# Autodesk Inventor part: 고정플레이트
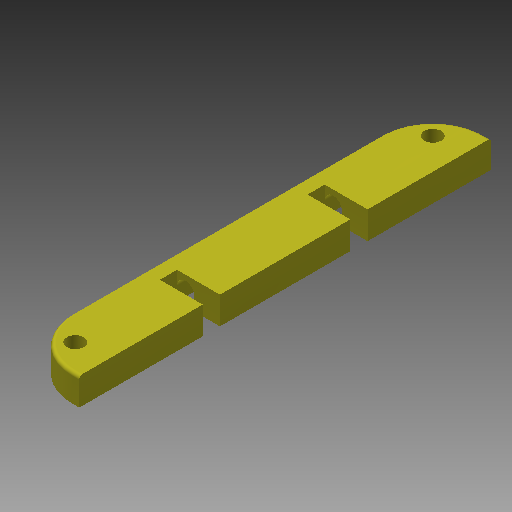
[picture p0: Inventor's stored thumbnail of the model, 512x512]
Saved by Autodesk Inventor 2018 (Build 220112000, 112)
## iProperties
Created: 2018-08
Part Number: 고정플레이트
Material: ABS 플라스틱
Document SubType Name: Modeling
Designer: mduedu
Density: 1 g/cm^3
Appearance: 밝은 황색
Author: mduedu
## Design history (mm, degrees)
sketch "스케치1"
  geometry: L1 (0, -60)-(17, -60); L2 (17, -60)-(17, 60); L3 (17, 60)-(0, 60); L4 (0, 60)-(0, -60); 2 further points
  constraints: 8 end point, 2 parallel, 1 coincident, 1 horizontal, 1 midpoint, 1 perpendicular
  dimensions: "d0" = 120 distance between parallel lines of L3 L1; "d2" = 17 distance of L1.start L1.end
extrude "돌출1" new body sketch "스케치1" distance "d3" = 8; taper "d4" = 0 deg
fillet "모깎기1" dims "d5" = 15
fillet "모깎기2" dims "d6" = 1
sketch "스케치2"
  geometry: L1 (-17, 0)-(-17, 7) reference; L2 (0, 0)-(-17, 0) reference; L3 (-12.5, 4)-(-12.5, 0); L4 (-7.5, 4)-(-7.5, 0); A1 r 2.5 centre (-10, 4) between (-12.5, 4) and (-7.5, 4)
  constraints: 4 end point, 2 perpendicular, 2 point on circle, 2 point on line, 2 tangent, 1 centre point
  dimensions: "d7" = 5 diameter of A1; "d8" = 7 distance from line of A1.centre L1; "d9" = 4 distance from line of L2 A1.centre
extrude "돌출2" cut sketch "스케치2" stored distance "d10" = 70; taper "d11" = 0 deg
fillet "모깎기3" dims "d12" = 2.5
sketch "스케치3"
  geometry: L1 (-12.5, -19)-(0, -19); L2 (0, -19)-(0, -24); L3 (0, -24)-(-12.5, -24); L4 (-12.5, -24)-(-12.5, -19); L5 (0, -59)-(0, 59) reference; L6 (-17, 45)-(-17, -45) reference; 2 further points
  constraints: 8 end point, 2 parallel, 1 horizontal, 1 midpoint, 1 perpendicular, 1 vertical alignment
  dimensions: "d13" = 4.5 distance between parallel lines of L4 L6; "d14" = 19 distance from line of L1 point (0, 0); "d15" = 5 distance of L1.end L2.end
extrude "돌출3" cut sketch "스케치3" extent not by distance; stored distance "d16" = 70; taper "d17" = 0 deg
sketch "스케치4"
  geometry: A1 r 15 centre (-2, -45) between (-17, -45) and (-2, -60) reference; A2 r 15 centre (-2, 45) between (-2, 60) and (-17, 45) reference; A3 r 10 centre (-2, 45) between (-2, 55) and (-12, 45); A4 r 10 centre (-2, -45) between (-12, -45) and (-2, -55); 3 further points
  constraints: 6 point on circle, 2 centre point, 2 horizontal alignment, 2 vertical alignment
  dimensions: "d18" = 5 radial gap between concentric circles of A3 A2; "d19" = 5 radial gap between concentric circles of A1 A4
hole "구멍1" sketch "스케치4" at (-9.071, 52.071), (-9.071, -52.071) diameter "d20" = 5; stored, may be unused: countersink angle "d24" = 90 deg, drill point angle "d26" = 118 deg; dims "d21" = 6, "d22" = 4, "d23" = 2, "d25" = 8
node "솔리드1"
mirror "대칭1"
